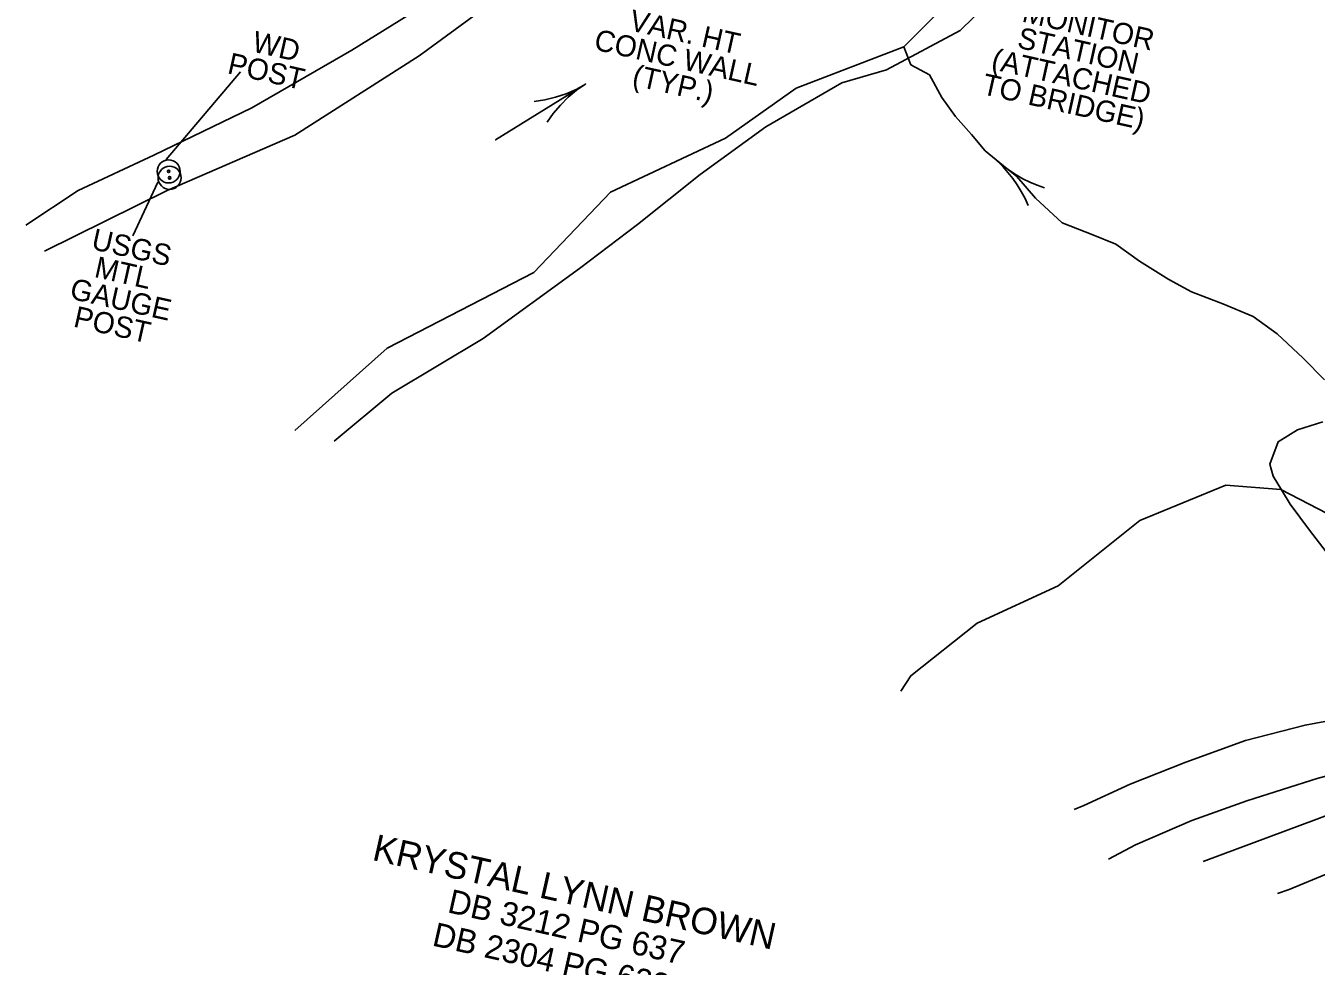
# Model space of a CAD drawing. Extents: x 1784037 to 1786391, y 840555 to 842045.
# Drawn here: x 1785323.7 to 1785567.5, y 841214.2 to 841391.7 of the extents above; entities that cross this region are included whole.
import ezdxf

# ---------------------------------------------------------------- set-up
doc = ezdxf.new("R2010")
doc.units = 0
for name, color, linetype in [('Exist Hydro River Flow Arrow CELL', 7, 'Continuous'), ('Exist Hydro Stream Flow Arrow CELL', 7, 'Continuous'), ('Exist Hydro Stream or Body of Water', 7, 'Continuous'), ('Exist Other Culture Dam', 7, 'Continuous'), ('Exist Other Culture Located Object CELL', 7, 'Continuous'), ('Exist Other Culture Located Object Leader', 7, 'Continuous'), ('Exist Other Culture Located Object Text', 7, 'Continuous'), ('Exist Property Deed Book Text', 7, 'Continuous'), ('Exist Property Owner Text', 7, 'Continuous'), ('Exist Roads Soil', 7, 'Continuous'), ('Exist Structure Major Bridge WW Text', 7, 'Continuous'), ('Exist Utilities Water Test Hole SUE LOS A Cogo Number', 7, 'Continuous'), ('Exist Vegetation Woods Line', 7, 'Continuous')]:
    doc.layers.add(name, color=color, linetype=linetype)

msp = doc.modelspace()

# ---------------------------------------------------------------- linework, layer by layer
at = {"layer": 'Exist Hydro River Flow Arrow CELL'}
msp.add_line((1785420.98, 841375.48), (1785420.98, 841375.48), dxfattribs=at)
msp.add_lwpolyline([(1785419.77, 841377.42), (1785421.79, 841377.75), (1785423.81, 841378.25), (1785425.79, 841378.92), (1785427.69, 841379.74), (1785429.48, 841380.75), (1785412.48, 841370.2), (1785429.48, 841380.75), (1785427.77, 841379.61), (1785426.2, 841378.26), (1785424.72, 841376.78), (1785423.37, 841375.2), (1785422.19, 841373.54)], dxfattribs=at)
at = {"layer": 'Exist Hydro Stream Flow Arrow CELL'}
msp.add_line((1785510.92, 841362.85), (1785510.92, 841362.85), dxfattribs=at)
for points in [[(1785516.15, 841361.15), (1785514.76, 841361.62), (1785513.4, 841362.24), (1785512.06, 841362.87), (1785510.81, 841363.6), (1785509.57, 841364.41), (1785508.37, 841365.3), (1785507.24, 841366.23)], [(1785513.06, 841357.78), (1785512.48, 841359.13), (1785511.74, 841360.44), (1785511, 841361.71), (1785510.17, 841362.9), (1785509.25, 841364.06), (1785508.27, 841365.19), (1785507.24, 841366.23)]]:
    msp.add_lwpolyline(points, dxfattribs=at)
at = {"layer": 'Exist Hydro Stream or Body of Water'}
for points in [[(1785569.06, 841324.9), (1785565, 841328.99), (1785560.09, 841333.61), (1785555.55, 841336.85), (1785549.82, 841339.27), (1785543.94, 841341.54), (1785539.61, 841343.85), (1785534.12, 841347.33), (1785529.62, 841350.51), (1785525.3, 841352.3), (1785519.47, 841354.51), (1785514.43, 841359.17), (1785510.95, 841363.3), (1785508.42, 841365.27), (1785504.93, 841368.16), (1785502.35, 841371.2), (1785499.35, 841374.63), (1785496.78, 841378.22), (1785494.45, 841382.48), (1785490.9, 841384.37), (1785489.58, 841387.79)], [(1785569.37, 841292.43), (1785566.19, 841296.54), (1785562.54, 841301.4), (1785560.94, 841304.11), (1785559.37, 841306.7), (1785558.69, 841308.96), (1785560.3, 841313.19), (1785563.93, 841315.44), (1785568.72, 841316.94)], [(1785560.14, 841227.91), (1785562.39, 841228.67), (1785569.38, 841231.57), (1785573.81, 841234.31), (1785575.77, 841236.16), (1785580.74, 841237.46), (1785582.6, 841238.12), (1785583.41, 841240.26), (1785583.53, 841242.13), (1785584.24, 841243.49), (1785588.57, 841244.61), (1785590.49, 841245.19)]]:
    msp.add_lwpolyline(points, dxfattribs=at)
at = {"layer": 'Exist Other Culture Dam'}
msp.add_lwpolyline([(1785546.13, 841233.95), (1785583.14, 841247.75), (1785603.5, 841252.78), (1785621.29, 841252.7), (1785647.55, 841244.05), (1785671.74, 841236.82)], dxfattribs=at)
at = {"layer": 'Exist Other Culture Located Object CELL'}
for centre, radius in [((1785350.72, 841364.25), 2.18), ((1785350.9, 841363.04), 2.18), ((1785350.72, 841364.25), 0.24), ((1785350.9, 841363.04), 0.24)]:
    msp.add_circle(centre, radius, dxfattribs=at)
at = {"layer": 'Exist Other Culture Located Object Leader'}
for p, q in [((1785350.27, 841366.48), (1785364.31, 841383.06)), ((1785348.69, 841362.22), (1785343.98, 841352.08))]:
    msp.add_line(p, q, dxfattribs=at)
at = {"layer": 'Exist Roads Soil'}
for points in [[(1785521.78, 841243.74), (1785523.6, 841244.5), (1785532.36, 841248.53), (1785542.85, 841252.68), (1785554.14, 841256.83), (1785565.36, 841259.72), (1785576.87, 841261.85), (1785584.98, 841263.6), (1785594.61, 841265.95), (1785602.17, 841267.9), (1785608.58, 841270.51), (1785619.17, 841274.32), (1785631.57, 841280.01), (1785640.45, 841283.67), (1785650.01, 841287.99), (1785660.2, 841293.53), (1785665.62, 841297.56), (1785669.23, 841301.5), (1785671.85, 841307.12), (1785672.45, 841309.73)], [(1785528.23, 841234.37), (1785533.31, 841237.07), (1785543.95, 841241.69), (1785554.36, 841245.38), (1785567.86, 841249.67), (1785580.02, 841252.85), (1785591.8, 841255.96), (1785600.06, 841257.55), (1785606.87, 841258.34), (1785615.12, 841257.98), (1785629.8, 841255.52), (1785642.44, 841252.45), (1785653.94, 841248.79), (1785664.51, 841246.05), (1785672.92, 841244.67), (1785679.79, 841244.71), (1785688.61, 841245.93), (1785696.59, 841246.1), (1785701.2, 841245.27)]]:
    msp.add_lwpolyline(points, dxfattribs=at)
at = {"layer": 'Exist Utilities Water Test Hole SUE LOS A Cogo Number'}
for points in [[(1785489.58, 841387.79), (1785506.25, 841404.56), (1785521.34, 841419.11), (1785531.25, 841431.86), (1785552.58, 841440.72), (1785554.58, 841442.11)], [(1785327.24, 841349.19), (1785350.43, 841360.62), (1785374.58, 841371.08), (1785398.06, 841386.06), (1785415.15, 841398.63), (1785436.41, 841409.84)], [(1785374.54, 841315.36), (1785392.01, 841330.87), (1785419.7, 841345.16), (1785434.15, 841360.34), (1785455.93, 841370.54), (1785469.25, 841379.98), (1785489.58, 841387.79)]]:
    msp.add_lwpolyline(points, dxfattribs=at)
at = {"layer": 'Exist Vegetation Woods Line'}
for points in [[(1785382, 841313.34), (1785392.87, 841322.38), (1785410.11, 841332.67), (1785428.33, 841345.92), (1785439.29, 841354.21), (1785451.14, 841363.64), (1785463.52, 841372.68), (1785477.9, 841380.96), (1785486.31, 841383.42), (1785500.25, 841390.85), (1785515.2, 841405.53), (1785527.17, 841415.48), (1785539.72, 841421.95), (1785557.37, 841428.59), (1785570.39, 841427.86)], [(1785411.31, 841403.32), (1785385.34, 841387.17), (1785366.45, 841376.22), (1785347.9, 841367.3), (1785333.62, 841360.65), (1785323.74, 841354.08)], [(1785573.09, 841297.82), (1785560.8, 841304.2), (1785550.43, 841305.03), (1785534.18, 841298.36), (1785518.71, 841286.03), (1785503.44, 841278.93), (1785490.91, 841269.02), (1785489.01, 841266.12)]]:
    msp.add_lwpolyline(points, dxfattribs=at)

# ---------------------------------------------------------------- texts
at = {"layer": 'Exist Other Culture Located Object Text'}
for s, p in [('MONITOR', (1785511.72, 841392.56)), ('WD', (1785366.3, 841386.9)), ('STATION', (1785510.8, 841387.64)), ('POST', (1785361.64, 841382.81)), ('(ATTACHED', (1785505.9, 841383.6)), ('TO BRIDGE)', (1785504.13, 841378.87)), ('USGS', (1785335.93, 841349.61)), ('MTL', (1785336.49, 841344.35)), ('GAUGE', (1785331.85, 841340.26)), ('POST', (1785332.55, 841334.97))]:
    msp.add_text(s, height=4, rotation=347.3599, dxfattribs=at).set_placement(p)
at = {"layer": 'Exist Property Deed Book Text'}
for s, p in [('DB 3212 PG 637', (1785403.2, 841224.39)), ('DB 2304 PG 623', (1785400.31, 841218.12))]:
    msp.add_text(s, height=4.5, rotation=347.3599, dxfattribs=at).set_placement(p)
at = {"layer": 'Exist Property Owner Text'}
msp.add_text('KRYSTAL LYNN BROWN', height=5, rotation=347.3599, dxfattribs=at).set_placement((1785388.98, 841234.27))
at = {"layer": 'Exist Structure Major Bridge WW Text'}
for s, p in [('VAR. HT', (1785437.52, 841390.93)), ('CONC WALL', (1785430.86, 841387.29)), ('(TYP.)', (1785438.07, 841380.55))]:
    msp.add_text(s, height=4, rotation=347.3599, dxfattribs=at).set_placement(p)

doc.saveas('drawing.dxf')
